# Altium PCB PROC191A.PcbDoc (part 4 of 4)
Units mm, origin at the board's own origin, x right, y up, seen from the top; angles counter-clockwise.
Board outline 150 x 100 mm, 6 copper layers (L1, L2, L3, L4, L5, L6), stack 1.608 mm thick; 309 components, 191 nets, 851 pads, 778 vias.
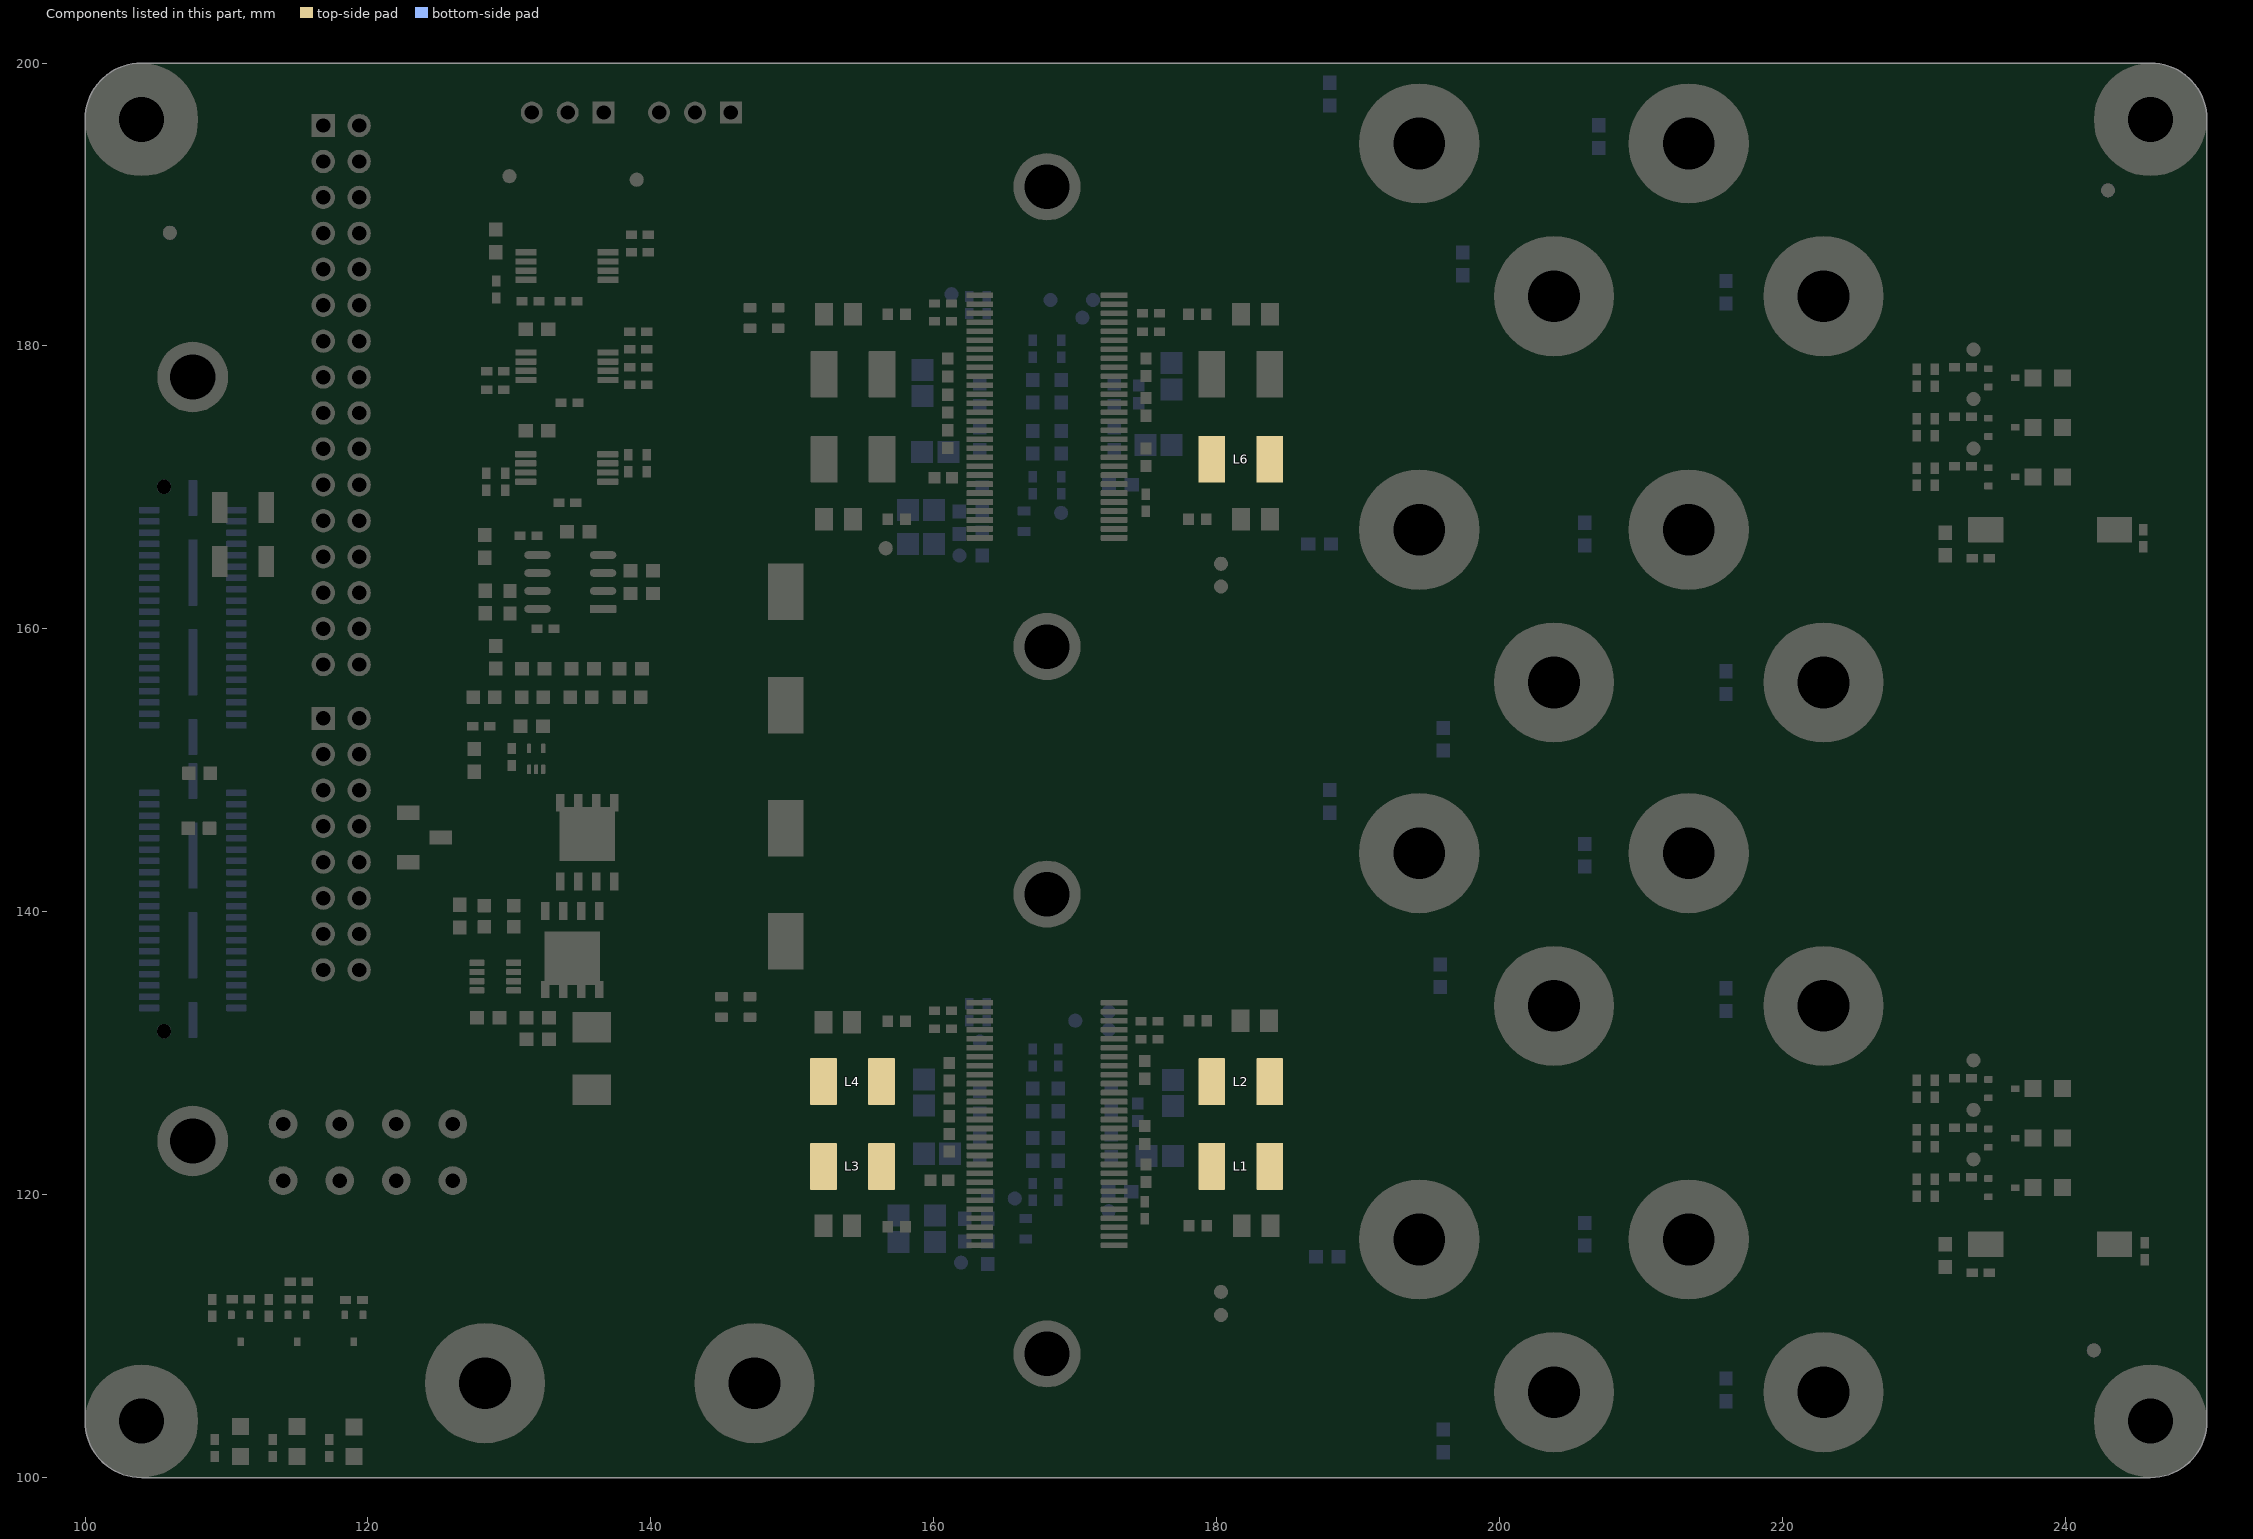
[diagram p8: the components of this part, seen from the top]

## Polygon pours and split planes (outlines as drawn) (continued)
PVDD on L3 "L3_PVDD_P025" (solid, remove dead copper, pour order 25): 131.911,150 131.911,142 158.5,142 160.5,144 160.5,156.5 158.5,158.5 142,158.5 140,156.5 140,150
OUT_1P_J1 on L3 "L3_OUT_1P_J1_P032" (solid, remove dead copper, pour order 32): 150.75,130.5 154.5,130.5 154.5,134.5 156,136 170.5,136 170.5,138.25 153.26,138.25 150.75,135.74
OUT_2P_J1 on L3 "L3_OUT_2P_J1_P033" (solid, remove dead copper, pour order 33): 150.546,119.494 154.296,119.494 154.296,115.744 156.04,114 170.296,114 170.296,111.5 153.299,111.5 150.546,114.253
PVDD_CONN on L3 "L3_PVDD_CONN_P040" (solid, remove dead copper, pour order 40): 137.449,139 131.911,139 131.911,100 153.015,100 153.015,111.21 150.225,114 150.225,125.829 140,135.604 140,139
VDDIO on L3 "L3_VDDIO_P050" (solid, remove dead copper, pour order 50): 114,128 151,128 153.31,130.31 153.31,190.5 118,190.5 110.49,182.99 110.49,154 113,154 113,129
OUT_1M_J1 on L3 "L3_OUT_1M_J1_P065" (solid, remove dead copper, pour order 65): 166,128 166,129.75 164,131.75 156.75,131.75 156.75,133.5 170.5,133.5 170.5,135.75 156,135.75 154.5,134.25 154.5,130.5 155.5,129.5 162,129.5 163.5,128
OUT_2M_J1 on L3 "L3_OUT_2M_J1_P066" (solid, remove dead copper, pour order 66): 166,121.976 166,120.254 163.746,118 156.75,118 156.75,116.463 170.5,116.463 170.5,114.226 156,114.226 154.5,115.726 154.5,118.726 156.024,120.25 162.024,120.25 163.75,121.976
OUT_4P_J1 on L3 "L3_OUT_4P_J1_P067" (solid, remove dead copper, pour order 67): 194.5,114.5 194.5,119.75 185.75,119.75 185.75,117 188.25,114.5
OUT_4M_J1 on L3 "L3_OUT_4M_J1_P069" (solid, remove dead copper, pour order 69): 185.5,124.5 211.5,124.5 216.5,119.5 210.75,113.75 207.533,117 196.75,117 193.75,120 185.5,120
OUT_3P0 on L3 "L3_OUT_3P0_P075" (solid, remove dead copper, pour order 75): 169.75,175 174.547,175 176.047,176.5 178.692,176.5 178.692,179.5 175.75,179.5 173,176.75 169.75,176.75
OUT_1P0 on L3 "L3_OUT_1P0_P078" (solid, remove dead copper, pour order 78): 166.102,176.75 166.102,175 160.809,175 159.691,176.5 157,176.5 157,179.5 159.75,179.5 162.042,176.75
OUT_2P0 on L3 "L3_OUT_2P0_P080" (solid, remove dead copper, pour order 80): 166.102,175 160.75,175 159.25,173.5 157,173.5 157,170.551 159.949,170.551 162.5,173.25 166.102,173.25
OUT_4P0 on L3 "L3_OUT_4P0_P085" (solid, remove dead copper, pour order 85): 169.75,173.25 169.75,175 174.562,175 175.812,173.75 178.692,173.75 178.692,170.75 175.75,170.75 173.25,173.25
OUT_3P_J1 on L3 "L3_OUT_3P_J1_P118" (solid, remove dead copper, pour order 118): 206,135.5 206,130.5 185.5,130.5 185.5,133 188,135.5
OUT_4M_J1 on L3 "L3_OUT_4M_J1_P119" (solid, remove dead copper, pour order 119): 170,122.75 173,122.75 175.25,120.5 178,120.5 182,124.5 186.25,124.5 186.25,120 183.75,120 180.75,117 175.25,117 171.5,120.75 170,120.75
OUT_3M_J1 on L3 "L3_OUT_3M_J1_P121" (solid, remove dead copper, pour order 121): 170,127.75 173,127.75 175,129.75 178.5,129.75 182.25,126 186.25,126 186.25,130.25 183.75,130.25 180.75,133.25 175,133.25 171.5,129.75 170,129.75
OUT_3P1 on L3 "L3_OUT_3P1_P122" (solid, remove dead copper, pour order 122): 169.75,125 174.547,125 176.047,126.5 178.692,126.5 178.692,129.5 175.75,129.5 173,126.75 169.75,126.75
OUT_1P1 on L3 "L3_OUT_1P1_P123" (solid, remove dead copper, pour order 123): 166.102,126.75 166.102,125 160.809,125 159.691,126.5 157,126.5 157,129.5 159.75,129.5 162.042,126.75
OUT_2P1 on L3 "L3_OUT_2P1_P124" (solid, remove dead copper, pour order 124): 166.102,125 160.75,125 159.25,123.5 157,123.5 157,120.551 159.949,120.551 162.5,123.25 166.102,123.25
OUT_3P_J1 on L3 "L3_OUT_3P_J1_P125" (solid, remove dead copper, pour order 125): 182.75,130.5 182.75,133.125 187,133.125 187,130.5
OUT_4P_J1 on L3 "L3_OUT_4P_J1_P126" (solid, remove dead copper, pour order 126): 182.75,117 182.75,119.75 187,119.75 187,117
OUT_4P1 on L3 "L3_OUT_4P1_P127" (solid, remove dead copper, pour order 127): 169.75,123.25 169.75,125 174.562,125 175.812,123.75 178.692,123.75 178.692,120.75 175.75,120.75 173.25,123.25
OUT_2P_J1 on L3 "L3_OUT_2P_J1_P128" (solid, remove dead copper, pour order 128): 170,111.5 179.29,102.21 203.835,102.21 203.835,110.21 182.79,110.21 179,114 170,114
OUT_1M_J1 on L3 "L3_OUT_1M_J1_P129" (solid, remove dead copper, pour order 129): 170,135.75 180,135.75 184.5,140.25 194,140.25 198,144.25 207.75,144.25 210.75,147.25 216.375,141.625 211.75,137 187.25,137 183.75,133.5 170,133.5
OUT_3M_J1 on L3 "L3_OUT_3M_J1_P130" (solid, remove dead copper, pour order 130): 185.5,126 221,126 226,131 220.25,136.75 217,133.5 207.405,133.5 204.155,130.25 185.5,130.25
OUT_2M_J1 on L3 "L3_OUT_2M_J1_P139" (solid, remove dead copper, pour order 139): 170,116.447 170,114.226 178.774,114.226 182.75,110.25 202.5,110.25 206.5,106.25 217.5,106.25 220.25,103.25 225.875,108.875 221,113.75 185.5,113.75 182.803,116.447 179.5,116.447
OUT_1P_J1 on L3 "L3_OUT_1P_J1_P141" (solid, remove dead copper, pour order 141): 170,138.25 180,148.25 194.31,148.25 194.31,140.25 184.5,140.25 180.25,136 170,136
GND on L3 "L3_GND_P145" (solid, remove dead copper, pour order 145): 104,200 246,200 cw(c246,196) 250,196 250,104 cw(c246,104) 246,100 104,100 cw(c104,104) 100,104 100,196 cw(c104,196)
GND on L4 "L4_GND_P185" (solid, remove dead copper, pour order 185): 104,200 246,200 cw(c246,196) 250,196 250,104 cw(c246,104) 246,100 104,100 cw(c104,104) 100,104 100,196 cw(c104,196)
VSYS5V0 on L4 "L4_VSYS5V0_P143" (solid, remove dead copper, pour order 143): 172,193 172,196 172.5,196.5 184.5,196.5 190.5,190.5 230,190.5 230.458,190.042 230.458,187.458 230,187 190,187 184.5,192.5 172.5,192.5
VDDIO on L4 "L4_VDDIO_P144" (solid, remove dead copper, pour order 144): 161,183.5 161.5,183 180,183 185,178 218.25,178 218.75,177.5 218.75,175.5 218.25,175 184,175 179,180 161,180
PVDD on L4 "L4_PVDD_P184" (solid, remove dead copper, pour order 184): 148.47,146.47 163.53,146.47 176.5,133.5 176.5,117 174.5,115 148.5,115 147.25,116.25 147.25,145.25
VDDIO on L4 "L4_VDDIO_P150" (solid, remove dead copper, pour order 150): 162,131 162,133.5 161,134.5 146.5,134.5 145.5,133.5 145.5,131 146.5,130 161,130
VDDIO on L4 "L4_VDDIO_P154" (solid, remove dead copper, pour order 154): 162,180 162,182.5 161,183.5 148.5,183.5 147.5,182.5 147.5,180 148.5,179 161,179
PVDD on L4 "L4_PVDD_P169" (solid, remove dead copper, pour order 169): 149,180 175,180 176.75,178.25 176.75,153.75 174.5,151.5 148.5,151.5 147.5,152.5 147.5,178.5
PVDD_CONN on L2 "L2_PVDD_CONN_P022" (solid, remove dead copper, pour order 22): 132.444,138.342 136.444,138.342 136.444,135.342 132.444,135.342
PVDD on L2 "L2_PVDD_P146" (solid, remove dead copper, pour order 146): 156.351,157.414 159.541,157.414 159.541,154.269 156.351,154.269
GND on L2 "L2_GND_P172" (solid, remove dead copper, pour order 172): 104,200 246,200 cw(c246,196) 250,196 250,104 cw(c246,104) 246,100 104,100 cw(c104,104) 100,104 100,196 cw(c104,196)
PVDD on L2 "L2_PVDD_P171" (solid, remove dead copper, pour order 171): 133.5,147 137.5,147 137.5,144 133.5,144
PVDD on L2 "L2_PVDD_P024" (solid, remove dead copper, pour order 24): 156.351,146.264 159.541,146.264 159.541,143.119 156.351,143.119
GND on L6 "L6_GND_P175" (solid, remove dead copper, pour order 175): 104,200 246,200 cw(c246,196) 250,196 250,104 cw(c246,104) 246,100 104,100 cw(c104,104) 100,104 100,196 cw(c104,196)
VDDIO on L6 "L6_VDDIO_P152" (solid, remove dead copper, pour order 152): 110,166.5 113,166.5 113,162.8 110,162.8
VSYS5V0 on L6 "L6_VSYS5V0_P148" (solid, remove dead copper, pour order 148): 110,170.5 113,170.5 113,166.5 110,166.5
PVDD on L6 "L6_PVDD_P035" (solid, remove dead copper, pour order 35): 175.6,177.3 177.8,177.3 177.8,173.5 175.6,173.5
PVDD on L6 "L6_PVDD_P034" (solid, remove dead copper, pour order 34): 158.3,176.9 160.5,176.9 160.5,173.1 158.3,173.1
PVDD on L6 "L6_PVDD_P138" (solid, remove dead copper, pour order 138): 175.517,126.8 177.7,126.8 177.7,123 175.517,123
PVDD on L6 "L6_PVDD_P137" (solid, remove dead copper, pour order 137): 160.483,122.65 158.3,122.65 158.3,126.8 160.483,126.8
OUT_2P1 on L6 "L6_OUT_2P1_P136" (solid, remove dead copper, pour order 136): 168,123.5 162.75,123.5 162.75,125 168,125
OUT_4P1 on L6 "L6_OUT_4P1_P135" (solid, remove dead copper, pour order 135): 168,125 173.25,125 173.25,123.5 168,123.5
OUT_1P1 on L6 "L6_OUT_1P1_P110" (solid, remove dead copper, pour order 110): 168,125 162.75,125 162.75,126.5 168,126.5
OUT_3P1 on L6 "L6_OUT_3P1_P109" (solid, remove dead copper, pour order 109): 168,126.5 173.25,126.5 173.25,125 168,125
OUT_2P0 on L6 "L6_OUT_2P0_P108" (solid, remove dead copper, pour order 108): 167.796,173.5 162.75,173.5 162.75,175 167.796,175
OUT_3P0 on L6 "L6_OUT_3P0_P036" (solid, remove dead copper, pour order 36): 168,176.5 173.25,176.5 173.25,175 168,175
OUT_4P0 on L6 "L6_OUT_4P0_P107" (solid, remove dead copper, pour order 107): 168,175 173.25,175 173.25,173.5 168,173.5
OUT_1P0 on L6 "L6_OUT_1P0_P037" (solid, remove dead copper, pour order 37): 168,175 162.75,175 162.75,176.5 168,176.5
GND on L5 "L5_GND_P174" (solid, remove dead copper, pour order 174): 104,200 246,200 cw(c246,196) 250,196 250,104 cw(c246,104) 246,100 104,100 cw(c104,104) 100,104 100,196 cw(c104,196)

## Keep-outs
Keep-Out Layer:
  text ".Layer_Name" at 14.656,-21.806 h1.52

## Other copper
L1:
  text ".Layer_Name" at 14.656,-21.806 h1.52
L6:
  text ".Layer_Name" at 14.656,-21.806 h1.52

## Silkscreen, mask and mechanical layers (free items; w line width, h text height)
Top Overlay:
  rectangle: 236,161 238,162.5
  rectangle: 240,163 242,164.5
  rectangle: 240,112.5 242,114
  rectangle: 236,110.5 238,112
  lines w0.2: 201.5,113.34 cw(c201.5,114.84) 201.5,116.34 cw(c201.5,114.84) 201.5,113.34 ; 201.5,140.645 cw(c201.5,142.145) 201.5,143.645 cw(c201.5,142.145) 201.5,140.645 ; 201.5,163.5 cw(c201.5,165) 201.5,166.5 cw(c201.5,165) 201.5,163.5 ; 201.5,190.81 ccw(c201.5,192.31) 201.5,193.81 ccw(c201.5,192.31) 201.5,190.81 ; 206.17,113.34 cw(c206.17,114.84) 206.17,116.34 cw(c206.17,114.84) 206.17,113.34 ; 206.17,140.645 cw(c206.17,142.145) 206.17,143.645 cw(c206.17,142.145) 206.17,140.645 ; 206.17,190.81 ccw(c206.17,192.31) 206.17,193.81 ccw(c206.17,192.31) 206.17,190.81 ; 206.34,163.51 cw(c206.34,165.01) 206.34,166.51 cw(c206.34,165.01) 206.34,163.51 ; 211,180.015 cw(c211,181.515) 211,183.015 cw(c211,181.515) 211,180.015 ; 211.025,102.545 cw(c211.025,104.045) 211.025,105.545 cw(c211.025,104.045) 211.025,102.545 ; 211.025,129.85 cw(c211.025,131.35) 211.025,132.85 cw(c211.025,131.35) 211.025,129.85 ; 211.025,152.71 cw(c211.025,154.21) 211.025,155.71 cw(c211.025,154.21) 211.025,152.71 ; 215.5,180.015 cw(c215.5,181.515) 215.5,183.015 cw(c215.5,181.515) 215.5,180.015 ; 215.695,102.545 cw(c215.695,104.045) 215.695,105.545 cw(c215.695,104.045) 215.695,102.545 ; 215.695,129.85 cw(c215.695,131.35) 215.695,132.85 cw(c215.695,131.35) 215.695,129.85 ; 215.695,152.71 cw(c215.695,154.21) 215.695,155.71 cw(c215.695,154.21) 215.695,152.71 ; 222,113.84 cw(c222,116.84) 222,119.84 227,119.84 cw(c227,116.84) 227,113.84 222,113.84 ; 222,164.005 cw(c222,167.005) 222,170.005 227,170.005 cw(c227,167.005) 227,164.005 222,164.005 ; 223,141.145 cw(c223,144.145) 223,147.145 228,147.145 cw(c228,144.145) 228,141.145 223,141.145 ; 223,190.31 cw(c223,193.31) 223,196.31 228,196.31 cw(c228,193.31) 228,190.31 223,190.31 ; 232.525,130.35 cw(c232.525,133.35) 232.525,136.35 237.525,136.35 cw(c237.525,133.35) 237.525,130.35 232.525,130.35 ; 232.525,153.21 cw(c232.525,156.21) 232.525,159.21 237.525,159.21 cw(c237.525,156.21) 237.525,153.21 232.525,153.21 ; 232.525,180.515 cw(c232.525,183.515) 232.525,186.515 237.525,186.515 cw(c237.525,183.515) 237.525,180.515 232.525,180.515 ; 232.716,103.045 cw(c232.716,106.045) 232.716,109.045 237.716,109.045 cw(c237.716,106.045) 237.716,103.045 232.716,103.045
  lines w0.254: 125.5,143.5 126.5,143.5 ; 125.5,147 126.5,147 ; 140.5,150 158,150 244.5,150 ; 235.5,110.5 242.5,110.5 242.5,112 235.5,112 235.5,110.5 ; 235.5,112.5 242.5,112.5 242.5,114 235.5,114 235.5,112.5 ; 235.5,161 242.5,161 242.5,162.5 235.5,162.5 235.5,161 ; 235.5,163 242.5,163 242.5,164.5 235.5,164.5 235.5,163
  text "GND 1" at 111.863,195.199 h0.76
  text "2 GND" at 121.056,195.199 h0.76
  text "UART_TX 3" at 108.562,192.723 h0.76
  text "4 AECCLKOUT" at 121.056,192.659 h0.76
  text "T0-CH1" at 221.25,192.56 h1.5
  text "FAN0" at 130.96,191.92 h1
  text "FAN1" at 139.85,191.92 h1
  text "M" at 205.67,191.56 h1.5
  text "P" at 200.75,191.31 h1.5
  text "TAS0" at 180.25,190.75 h1.5
  text "MCASPX_ACLKR 5" at 104.753,190.183 h0.76
  text "6 AECCLKIN" at 121.056,190.119 h0.76
  text "GND 7" at 111.609,187.579 h0.76
  text "8 GND" at 121.056,187.579 h0.76
  text "MCASPX_FSX 9" at 106.276,185.103 h0.76
  text "10 FSYNC1" at 121.056,185.039 h0.76
  text "T0-CH3" at 230.775,182.765 h1.5
  text "MCASPX_FSR 11" at 105.896,182.563 h0.76
  text "12 FSYNC2" at 121.056,182.499 h0.76
  text "M" at 215,180.765 h1.5
  text "P" at 210.25,180.515 h1.5
  text "GND 13" at 110.974,179.959 h0.76
  text "14 GND" at 121.056,179.959 h0.76
  text "TAS0" at 142.65,179.15 h1
  text "I2C ADDR" at 142.65,177.65 h1
  text "15" at 114.021,177.419 h0.76
  text "16 I2CSCL" at 121.056,177.419 h0.76
  text "FLT" at 241.4,177.4 h1
  text "17" at 114.021,174.879 h0.76
  text "18 I2CSDA" at 121.056,174.879 h0.76
  text "SBY" at 241.25,173.5 h1
  text "TAS0 / STATUS" at 222.5,173 h1
  text "MCASPX_AR2 19" at 105.642,172.403 h0.76
  text "20 SPICLK" at 121.056,172.339 h0.76
  text "PWD" at 241.4,170.4 h1
  text "21" at 114.148,169.799 h0.76
  text "22 SPICS0" at 121.056,169.799 h0.76
  text "23" at 113.894,167.259 h0.76
  text "24 SPICS1" at 121.056,167.259 h0.76
  text "T0-CH4" at 220.25,166.255 h1.5
  text "25" at 113.894,164.719 h0.76
  text "26 SPID0" at 121.056,164.719 h0.76
  text "M" at 205.84,164.26 h1.5
  text "P" at 200.75,164 h1.5
  text "HIGH" at 243.15,163 h1
  text "28 SPID1" at 121.056,162.179 h0.76
  text "TAS0 GPIO1" at 225.418,161.65 h1
  text "MCASPX_S6 27" at 106.124,161.2 h0.76
  text "LOW" at 243.15,161 h1
  text "MCASPX_S7 29" at 106.276,159.703 h0.76
  text "30 UARTTX" at 120.904,158.75 h0.76
  text "GND 31" at 111.101,157.099 h0.76
  text "32 UARTRX" at 120.904,156.947 h0.76
  text "T0-CH2" at 230.775,155.46 h1.5
  text "M" at 215.195,153.46 h1.5
  text "MCASPY_ACLKX 1" at 105.007,153.337 h0.76
  text "2" at 121.056,153.289 h0.76
  text "P" at 210.275,153.21 h1.5
  text "PORZ" at 135.975,152.587 h1
  text "FANOUT" at 135.975,151.229 h1
  text "GND 3" at 111.609,150.749 h0.76
  text "4" at 121.057,150.749 h0.76
  text "5" at 114.656,148.209 h0.76
  text "6" at 121.057,148.209 h0.76
  text "RESET / STATZ" at 127,146.05 h1
  text "8" at 121.057,145.669 h0.76
  text "GND 7" at 111.456,144.1 h0.76
  text "T1-CH1" at 221.25,143.395 h1.5
  text "MCASPY_AFSX 9" at 105.515,143.193 h0.76
  text "PORZ" at 127.15,143.152 h1
  text ".PRJ_Title" at 233.15,142.15 h1
  text "M" at 205.67,141.395 h1.5
  text "P" at 200.75,141.145 h1.5
  text "TAS1" at 180.75,140.75 h1.5
  text "GND 11" at 111.228,140.589 h0.76
  text "12" at 121.056,140.589 h0.76
  text ".PRJ_Number" at 233.15,140.15 h1
  text ".PCB_Rev" at 240.15,140.15 h1
  text "MCASPY_AFSR 13" at 104.88,138.113 h0.76
  text "14" at 121.056,138.049 h0.76
  text "GND 15" at 110.974,135.509 h0.76
  text "16" at 121.133,135.509 h0.76
  text "T1-CH3" at 230.775,132.6 h1.5
  text "M" at 215.195,130.6 h1.5
  text "P" at 210.275,130.35 h1.5
  text "TAS1" at 142.15,129.65 h1
  text "I2C ADDR" at 142.15,128.15 h1
  text "FLT" at 241.4,127.15 h1
  text "PORZ" at 125.92,126.746 h1.52 r45
  text "GND" at 113.982,126.492 h1.52 r45
  text "GPIO1" at 118.046,126.492 h1.52 r45
  text "GPIO0" at 121.856,126.492 h1.52 r45
  text "SBY" at 241.4,123.65 h1
  text "TAS1 / STATUS" at 222.5,122.75 h1
  text "PWD" at 241.4,120.15 h1
  text "GND" at 112.712,116.84 h1.52 r45
  text "PVDD" at 124.142,116.332 h1.52 r45
  text "T1-CH4" at 220.25,116.09 h1.5
  text "VDDIO" at 119.824,115.824 h1.52 r45
  text "VSYS5V0" at 114.49,114.554 h1.52 r45
  text "M" at 205.67,114.09 h1.5
  text "P" at 200.75,113.84 h1.5
  text "HIGH" at 243.15,112.5 h1
  text "TAS1 GPIO1" at 226.001,112 h1
  text "GND" at 133.778,111.25 h1.5
  text "PVDD" at 151.7,111.25 h1.5
  text "LOW" at 243.15,110.5 h1
  text "PORZ" at 118.369,105.556 h1 r45
  text "IOVDD" at 109.635,105.512 h1 r45
  text "PVDD" at 114.35,105.512 h1 r45
  text "T1-CH2" at 230.966,105.295 h1.5
  text "M" at 215.195,103.295 h1.5
  text "P" at 210.275,103.045 h1.5
  text ".Layer_Name" at 14.656,-22.695 h1.52
Bottom Overlay:
  text ".Layer_Name" at 14.656,-21.806 h1.52
Top Paste:
  text ".Layer_Name" at 14.656,-21.806 h1.52
Bottom Paste:
  text ".Layer_Name" at 14.656,-21.806 h1.52
Top Solder:
  region: 240,100 240,101.5 241.5,103 250,103 250,100
  region: 156,100 156,101.5 157.5,103 193,103 194.5,101.5 194.5,100
  region: 103,100 100,100 100,128.5 101.5,128.5 103,127
  region: 100,197 100,200 113.5,200 113.5,198.5 112,197
  region: 149.5,198.5 149.5,200 185.5,200 185.5,198.5 184,197 151,197
  region: 219.5,198.5 219.5,200 250,200 250,197 221,197
  region: 101.5,137.5 100,137.5 100,200 103,200 103,139
  region: 250,100 247,100 247,200 250,200
  text ".Layer_Name" at 14.656,-21.806 h1.52
  text ".Layer_Name" at 14.656,-21.806 h1.52
Bottom Solder:
  region: 103,103 100,103 100,128.5 101.5,128.5 103,127
  region: 231,100 231,101.5 232.5,103 250,103 250,100
  region: 100,197 100,200 113.5,200 113.5,198.5 112,197
  region: 149.5,198.5 149.5,200 185.5,200 185.5,198.467 184.032,197 151,197
  region: 219.5,198.5 219.5,200 250,200 250,197 221,197
  region: 100,100 100,103 119,103 120.32,101.68 120.32,100
  region: 101.5,173.5 100,173.5 100,200 103,200 103,175
  region: 250,100 247,100 247,200 250,200
  region: 156,100 156,101.46 157.54,103 190.5,103 192,101.5 192,100
  text ".Layer_Name" at 14.656,-21.806 h1.52
Drill Guide:
  text ".Layer_Name" at 14.656,-21.806 h1.52
M1 Board Outline:
  the board outline again, w0.254
  text ".Layer_Name" at 14.656,-21.806 h1.52
M2 Board Dimensions:
  circle w0.254: c246,104 r1.6
  circle w0.254: c107.62,177.8 r1.6
  circle w0.254: c107.62,123.8 r1.6
  circle w0.254: c104,104 r1.6
  circle w0.254: c104,196 r1.6
  circle w0.254: c246,196 r1.6
  rectangle: 3.175,-10.16 12.7,-6.985
  rectangle: 0,-6.985 3.175,-3.81
  lines w0.178: 0,-6.985 25.4,-6.985 ; 3.175,-10.16 3.175,-3.81 ; 6.35,-10.16 6.35,-3.81 ; 12.7,-10.16 12.7,-3.81 ; 19.05,-10.16 19.05,-3.81 ; 0,-10.16 0,-3.81 25.4,-3.81 25.4,-10.16 0,-10.16
  lines w0.2: 89,152 90,151 ; 106.62,209 107.62,210 ; 119,218 120,219
  lines w0.254: 77,150.8 107.62,150.8 ; 86,154 90,154 90,151 91,152 ; 98.62,210 107.62,210 106.62,211 ; 99,123.8 107.62,123.8 ; 99,177.8 107.62,177.8 ; 99,219 120,219 119,220 ; 107.62,95 107.62,215 ; 107.62,170.9 107.62,205 ; 120,85 120.32,235
  text "BASEBOARD EDGE" at 77.152,218.152 h1.52
  text "VERT CENTERLINE  / AEC CONNECTOR" at 74,208.924 h1.52
  text "HORZ CENTERLINE  / AEC CONNECTOR" at 61.588,152 h1.52
  text ".Layer_Name" at 14.656,-21.806 h1.52
M3 3D STEP Top:
  text ".Layer_Name" at 14.656,-21.806 h1.52
M4 3D STEP Bottom:
  text ".Layer_Name" at 14.656,-21.806 h1.52
M5 Assembly Top:
  lines w0.254: -7.417,-23.626 160.223,-23.626 ; -7.417,-18.462 160.274,-18.462 ; -7.417,-13.297 -7.417,-28.791 94.31,-28.791 160.274,-28.791 160.274,-13.297 -7.404,-13.297 -7.404,-28.791 32.614,-28.791 ; 55.194,-28.791 55.194,-13.297 ; 87.376,-18.462 87.376,-13.297 ; 108.712,-18.462 108.712,-13.297 ; 124.511,-28.956 124.511,-23.804
  text "COMPONENTS MARKED 'DNP' SHOULD NOT BE POPULATED." at 29.299,-8.09 h1.52
  text "ASSEMBLY VARIANT:" at 29.286,-11.024 h1.52
  text ".VariantName" at 55.601,-11.024 h1.52
  text "PCB VIEWED FROM TOP SIDE" at -5.804,-16.654 h1.52
  text "BOARD #:" at 57.099,-16.654 h1.52
  text ".PRJ_Number" at 70.955,-16.654 h1.52
  text "REV:" at 92.405,-16.654 h1.52
  text ".PCB_Rev" at 99.809,-16.654 h1.52
  text "SVN REV:" at 113.69,-16.654 h1.52
  text ".VersionControl_RevNumber" at 126.543,-16.654 h1.52
  text "PLOT NAME =" at -5.804,-27.034 h1.52
  text ".plot_File_Name" at 14.656,-27.034 h1.52
  text "GENERATED    :" at 57.15,-27.034 h1.52
  text ".Print_Date" at 79.235,-27.034 h1.52
  text ".Print_Time" at 97.752,-27.034 h1.52
  text "TEXAS INSTRUMENTS" at 129.87,-27.034 h1.52
M6 Assembly Bottom:
  lines w0.254: -7.429,-18.474 160.261,-18.474 ; -7.379,-23.639 160.261,-23.639 ; 28.334,-28.969 28.334,-23.817 ; 44.133,-18.474 44.133,-13.31 ; 65.468,-18.474 65.468,-13.31 ; 97.65,-28.804 97.65,-13.31 ; 120.231,-28.804 160.249,-28.804 160.249,-13.31 -7.429,-13.31 -7.429,-28.804 58.534,-28.804 160.261,-28.804 160.261,-13.31
  text "COMPONENTS MARKED 'DNP' SHOULD NOT BE POPULATED." at 154.991,-8.077 h1.52
  text ".VariantName" at 128.473,-11.024 h1.52
  text "ASSEMBLY VARIANT:" at 154.864,-11.024 h1.52
  text ".VersionControl_RevNumber" at 26.302,-16.667 h1.52
  text "SVN REV:" at 39.154,-16.667 h1.52
  text ".PCB_Rev" at 53.035,-16.667 h1.52
  text "REV:" at 60.439,-16.667 h1.52
  text ".PRJ_Number" at 81.89,-16.667 h1.52
  text "BOARD #:" at 95.745,-16.667 h1.52
  text "PCB VIEWED FROM BOTTOM SIDE" at 158.648,-16.667 h1.52
  text "TEXAS INSTRUMENTS" at 22.974,-27.047 h1.52
  text ".Print_Time" at 55.093,-27.047 h1.52
  text ".Print_Date" at 73.609,-27.047 h1.52
  text "GENERATED    :" at 95.694,-27.047 h1.52
  text ".plot_File_Name" at 138.189,-27.047 h1.52
  text "PLOT NAME =" at 158.648,-27.047 h1.52
M9 Title Sheet:
  drawing of 63 lines, arcs and shapes, not listed
  text "1" at 35.293,466.75 h1.78
  text "2" at 136.766,466.75 h1.78
  text "3" at 238.239,466.75 h1.78
  text "4" at 339.865,466.75 h1.78
  text "5" at 441.423,466.75 h1.78
  text "6" at 542.98,466.75 h1.78
  text "7" at 644.623,466.75 h1.78
  text "8" at 746.096,466.75 h1.78
  text "A" at -11.874,405.841 h1.78
  text "A" at 793.305,405.841 h1.78
  text "B" at -11.874,278.841 h1.78
  text "B" at 793.305,278.841 h1.78
  text "C" at -11.874,151.841 h1.78
  text "C" at 793.305,151.841 h1.78
  text "D" at -11.874,24.841 h1.78
  text "D" at 793.305,24.841 h1.78
  text "PROJECT TITLE:" at 714.947,6.823 h1.14
  text ".PRJ_Title" at 716.216,3.436 h1.78
  text "DESIGNED FOR:" at 714.947,-0.823 h1.14
  text ".PRJ_Customer" at 716.216,-4.379 h1.78
  text "FILE NAME:" at 714.947,-8.443 h1.14
  text ".PCB_File_Name_No_Path" at 716.216,-11.491 h1.78
  text "Texas Instruments (TI) and/or its licensors do not warrant the accuracy or completeness of this specification" at 588.721,-15.601 h1.14
  text "ENGINEER:" at 714.947,-15.809 h1.14
  text "LAYOUT BY:" at 753.173,-15.809 h1.14
  text "or any information contained therein. TI and/or its licensors do not warrant that this design will meet" at 587.579,-18.463 h1.14
  text ".PRJ_Engineer" at 716.216,-19.746 h1.78
  text ".PCB_Layout" at 754.456,-19.746 h1.78
  text "the specifications, will be suitable for your application or fit for any particular purpose, or will operate in" at 587.579,-21.325 h1.14
  text ".Layer_Name" at 14.656,-21.806 h1.52
  text "ALTIUM DESIGNER VERSION:" at 753.173,-23.683 h1.14
  text "an implementation. TI and/or its licensors do not warrant that the design is production worthy. You should" at 587.579,-24.187 h1.14
  text "completely validate and test your design implementation to confirm the system functionality for your application." at 588.721,-27.048 h1.14
  text ".print_Scale" at 716.216,-27.069 h1.78
  text ".Application_BuildNumber" at 754.456,-27.069 h1.78
  text "1" at 35.293,-33.503 h1.78
  text "2" at 136.766,-33.503 h1.78
  text "3" at 238.239,-33.503 h1.78
  text "4" at 339.865,-33.503 h1.78
  text "5" at 441.423,-33.503 h1.78
  text "6" at 542.98,-33.503 h1.78
  text "7" at 644.623,-33.503 h1.78
  text "8" at 746.096,-33.503 h1.78
M10 Fab Notes:
  drawing of 189 lines, arcs and shapes, not listed
  text "DESIGN INFORMATION" at 741.376,161.675 h1.52
  text "MIN. TRACK WIDTH:" at 725.004,158.319 h1.52
  text "7" at 752.848,158.32 h1.52
  text "MM" at 756.779,158.319 h1.52
  text "MIN. CLEARANCE:" at 725.004,155.167 h1.52
  text "5" at 752.881,155.169 h1.52
  text "MIL" at 756.779,155.167 h1.52
  text "19" at 752.231,152.052 h1.52
  text "MIN. VIA PAD SIZE:" at 725.004,152.014 h1.52
  text "MIL" at 756.779,152.014 h1.52
  text "0.05mm (2MIL)" at 742.657,148.714 h1.52
  text "MINIMUM ANNULAR RING" at 716.641,148.506 h1.52
  text "EXTERNAL" at 760.64,148.506 h1.52
  text "PER" at 721.721,145.708 h1.52
  text "IPC-D-275 CLASS 2 LEVEL C" at 727.309,145.708 h1.52
  text "MIL, HOLES" at 765.11,143.156 h1.52
  text "+/-" at 755.142,142.938 h1.52
  text "+/-" at 776.834,142.938 h1.52
  text "REGISTRATION TOLERANCES:" at 716.641,142.911 h1.52
  text "METAL" at 747.116,142.911 h1.52
  text "5" at 761.751,142.911 h1.52
  text "3" at 782.909,142.911 h1.52
  text "MIL" at 785.862,142.911 h1.52
  text "HOLE SIZE TOLERANCE (UNLESS OTHERWISE SPECIFIED):" at 716.641,140.414 h1.52
  text "+/-" at 776.834,140.341 h1.52
  text "3" at 782.909,140.314 h1.52
  text "MIL" at 785.862,140.314 h1.52
  text "MATERIAL:" at 714.742,136.818 h1.52
  text "FR-4 High Tg" at 739.798,133.553 h1.52
  text "X" at 736.129,133.35 h1.52
  text "FR-4" at 725.436,133.235 h1.52
  text "OTHER" at 763.231,133.235 h1.52
  text "62 MIL (1.6mm) +/-10%" at 733.566,129.602 h1.52
  text "X" at 730.516,129.54 h1.52
  text "THICKNESS:" at 716.641,129.394 h1.52
  text "OTHER" at 766.203,129.394 h1.52
  text "TOLERANCE:" at 716.641,125.88 h1.52
  text "X" at 738.187,125.88 h1.52
  text "ANSI IPC-6012 TYPE 3 CLASS 2" at 742.708,125.88 h1.52
  text "OTHER +/-" at 742.708,122.218 h1.52
  text "BOW & TWIST:" at 716.641,118.53 h1.52
  text "X" at 738.187,118.53 h1.52
  text "ANSI IPC-6012 TYPE 3 CLASS 2" at 742.708,118.53 h1.52
  text "OTHER +/-" at 742.708,114.804 h1.52
  text "DRILLING:" at 714.742,111.486 h1.52
  text "NC_DRILL FILES" at 759.472,108.815 h1.52
  text "REFERENCE:" at 716.641,108.715 h1.52
  text "X" at 733.335,108.712 h1.52
  text "AS SHOWN" at 737.856,108.715 h1.52
  text "X" at 756.221,108.715 h1.52
  text "OTHER" at 767.041,105.101 h1.52
  text "PTH COPPER THICKNESS:" at 716.633,105.012 h1.52
  text "X" at 745.57,105.012 h1.52
  text "20-30 um" at 748.821,105.012 h1.52
  text "BOARD FINISH:" at 714.742,101.263 h1.52
  text "SILKSCREEN:" at 718.685,98.466 h1.52
  text "X" at 743.013,98.466 h1.52
  text "TOP" at 745.984,98.466 h1.52
  text "X" at 755.967,98.466 h1.52
  text "BOTTOM" at 758.964,98.466 h1.52
  text "SILKSCREEN COLOR:" at 718.685,94.524 h1.52
  text "WHITE" at 745.984,94.524 h1.52
  text "OTHER" at 758.964,94.524 h1.52
  text "X" at 743.136,94.482 h1.52
  text "X" at 762.416,92.464 h1.52 r180
  text "RED" at 773.615,90.905 h1.52
  text "GREEN" at 749.312,90.88 h1.52
  text "OTHER" at 765.009,90.88 h1.52
  text "SOLDER RESIST COLOR:" at 718.685,90.706 h1.52
  text "X" at 746.315,86.962 h1.52
  text "MATTE" at 749.312,86.962 h1.52
  text "SEMI-GLOSS" at 764.997,86.946 h1.52
  text "IMMERSION GOLD (ENIG)" at 741.692,82.574 h1.52
  text "ENEPIG" at 775.665,82.39 h1.52
  text "SURFACE FINISH:" at 714.742,82.365 h1.52
  text "X" at 737.171,82.365 h1.52
  text "IMM. TIN/SILVER OR EQUIV" at 723.113,78.877 h1.52
  text "OTHER" at 759.472,78.777 h1.52
  text "ARRAY/PANEL:" at 714.742,74.831 h1.52
  text "X" at 737.134,74.647 h1.52
  text "CUT AND TRIM PER M1 BOARD OUTLINE" at 741.692,74.622 h1.52
  text "N.C. ROUTE" at 741.692,71.168 h1.52
  text "V. SCORE" at 763.688,71.168 h1.52
  text "CERTIFICATION:" at 714.742,67.888 h1.52
  text "MATERIALS AND WORKMANSHIP FOR ALL PCBS" at 733.157,67.888 h1.52
  text "TO MEET OR EXCEED THE REQUIREMENTS OF:" at 733.157,65.499 h1.52
  text "X" at 723.95,62.232 h1.52
  text "ANSI IPC-A-600F CLASS ->" at 727.201,62.232 h1.52
  text "X" at 769.06,62.232 h1.52
  text "2" at 771.854,62.232 h1.52
  text "1" at 763.853,62.194 h1.52
  text "3" at 780.846,62.194 h1.52
  text "X" at 744.575,58.481 h1.52
  text "RoHS" at 747.826,58.481 h1.52
  text "OTHER" at 764.194,58.481 h1.52
  text "PER ORDER" at 774.279,58.481 h1.52
  text "ALL BOARDS MUST MEET OR EXCEED UL94-V0 REQUIREMENTS." at 715.442,54.574 h1.52
  text "PCB MUST BEAR THE UL94V-0 UL REGISTERED MATERIAL ID NUMBER" at 715.442,51.626 h1.52
  text "ADDITIONAL REQUIREMENTS:" at 714.742,47.322 h1.52
  text "MICROSECTION:" at 716.641,44.601 h1.52
  text "YES" at 739.647,44.601 h1.52
  text "REQUIRED" at 761.529,40.935 h1.52
  text "BARE BOARD ELEC. TEST:" at 716.641,40.863 h1.52
  text "NONE" at 749.807,40.863 h1.52
  text "X" at 758.532,40.863 h1.52
  text "PER ORDER" at 776.566,40.863 h1.52
  text "XX MIL VIAS REQUIRE NON-CONDUCTIVE FILL AND PLANARIZE" at 720.912,35.657 h1.5
  text "XX MIL VIAS REQUIRE CONDUCTIVE FILL AND PLANARIZE" at 721.116,33.016 h1.52
  text "OUTER XX MIL TRACES REQUIRE 50 OHM SINGLE-ENDED IMPEDANCE" at 721.091,28.866 h1.47
  text "LAYER 2 & 3 (INNER LAYERS) XX MIL WIDE, XX MIL SPACE / TRACES REQUIRE 100 OHM DIFFERENTIAL IMPEDANCE" at 720.887,22.879 h1.52
  text ".Layer_Name" at 14.656,-21.806 h1.52
M11 Gerber Information:
  lines w0.254: -7.417,-23.626 160.223,-23.626 ; -7.417,-18.462 160.274,-18.462 ; -7.417,-13.297 -7.417,-28.791 94.31,-28.791 160.274,-28.791 160.274,-13.297 -7.404,-13.297 -7.404,-28.791 32.614,-28.791 ; 55.194,-28.791 55.194,-13.297 ; 87.376,-18.462 87.376,-13.297 ; 108.712,-18.462 108.712,-13.297 ; 124.511,-28.956 124.511,-23.804
  text "ALL ARTWORK VIEWED FROM TOP SIDE" at -5.804,-16.654 h1.52
  text "BOARD #:" at 57.099,-16.654 h1.52
  text ".PRJ_Number" at 70.955,-16.654 h1.52
  text "REV:" at 92.405,-16.654 h1.52
  text ".PCB_Rev" at 99.809,-16.654 h1.52
  text "SVN REV:" at 113.69,-16.654 h1.52
  text ".VersionControl_RevNumber" at 126.543,-16.654 h1.52
  text "LAYER NAME =" at -5.804,-21.806 h1.52
  text "PLOT NAME =" at -5.804,-27.034 h1.52
  text ".plot_File_Name" at 14.656,-27.034 h1.52
  text "GENERATED    :" at 57.15,-27.034 h1.52
  text ".Print_Date" at 79.235,-27.034 h1.52
  text ".Print_Time" at 97.752,-27.034 h1.52
  text "TEXAS INSTRUMENTS" at 129.87,-27.034 h1.52
M12 Stackup:
  lines w0.381: 178.698,257.683 189.109,257.683 212.725,257.683 252.083,257.683 268.589,257.683 283.064,257.683 ; 178.698,260.731 189.109,260.731 212.725,260.731 252.083,260.731 268.589,260.731 283.064,260.731 ; 178.698,263.779 189.109,263.779 212.725,263.779 252.083,263.779 268.589,263.779 283.064,263.779 ; 178.698,266.827 189.109,266.827 212.725,266.827 252.083,266.827 268.589,266.827 283.064,266.827 ; 178.698,269.875 189.109,269.875 212.725,269.875 252.083,269.875 268.589,269.875 283.064,269.875 ; 178.698,272.923 189.109,272.923 212.725,272.923 252.083,272.923 268.589,272.923 283.064,272.923 ; 178.698,275.971 189.109,275.971 212.725,275.971 252.083,275.971 268.589,275.971 283.064,275.971 ; 178.698,279.019 189.109,279.019 212.725,279.019 252.083,279.019 268.589,279.019 283.064,279.019 ; 178.698,282.067 189.109,282.067 212.725,282.067 252.083,282.067 268.589,282.067 283.064,282.067 ; 178.698,285.115 189.109,285.115 212.725,285.115 252.083,285.115 268.589,285.115 283.064,285.115 ; 178.698,288.163 189.109,288.163 212.725,288.163 252.083,288.163 268.589,288.163 283.064,288.163 ; 178.698,291.211 189.109,291.211 212.725,291.211 252.083,291.211 268.589,291.211 283.064,291.211 ; 178.698,294.259 189.109,294.259 212.725,294.259 252.083,294.259 268.589,294.259 283.064,294.259 ; 178.698,297.307 189.109,297.307 212.725,297.307 252.083,297.307 268.589,297.307 283.064,297.307 ; 178.698,300.355 283.064,300.355 ; 189.109,303.403 189.109,254.635 ; 212.725,303.403 212.725,254.635 ; 252.083,303.403 252.083,254.635 ; 268.589,303.403 268.589,254.635 ; 189.109,254.635 178.698,254.635 178.698,303.403 283.064,303.403 283.064,254.635 268.589,254.635 ; 189.109,254.635 212.725,254.635 ; 212.725,254.635 252.083,254.635 ; 252.083,254.635 268.589,254.635
  text "Layer" at 180.476,301.117 h1.52
  text "Name" at 190.887,301.117 h1.52
  text "Material" at 214.503,301.117 h1.52
  text "Thickness" at 253.861,301.117 h1.52
  text "Constant" at 270.367,301.117 h1.52
  text "Top Overlay" at 190.887,298.069 h1.52
  text "Top Solder" at 190.887,295.021 h1.52
  text "Solder Resist" at 214.503,295.021 h1.52
  text "0.40mil" at 253.861,295.021 h1.52
  text "3.5" at 270.367,295.021 h1.52
  text "1" at 180.476,291.973 h1.52
  text "L1" at 190.887,291.973 h1.52
  text "Copper Foil, 1/2oz (17um)" at 214.503,291.973 h1.52
  text "0.71mil" at 253.861,291.973 h1.52
  text "Dielectric 1" at 190.887,288.925 h1.52
  text "Isola 370HR Core" at 214.503,288.925 h1.52
  text "3.94mil" at 253.861,288.925 h1.52
  text "4.17" at 270.367,288.925 h1.52
  text "2" at 180.476,285.877 h1.52
  text "L2" at 190.887,285.877 h1.52
  text "Copper Foil, 1/2oz (17um)" at 214.503,285.877 h1.52
  text "0.71mil" at 253.861,285.877 h1.52
  text "Dielectric 3" at 190.887,282.829 h1.52
  text "Isola 370HR Prepreg" at 214.503,282.829 h1.52
  text "5.91mil" at 253.861,282.829 h1.52
  text "4.17" at 270.367,282.829 h1.52
  text "3" at 180.476,279.781 h1.52
  text "L3" at 190.887,279.781 h1.52
  text "Copper Foil, 1/2oz (17um)" at 214.503,279.781 h1.52
  text "0.71mil" at 253.861,279.781 h1.52
  text "Dielectric1" at 190.887,276.733 h1.52
  text "Isola 370HR Core" at 214.503,276.733 h1.52
  text "39.37mil" at 253.861,276.733 h1.52
  text "4.17" at 270.367,276.733 h1.52
  text "4" at 180.476,273.685 h1.52
  text "L4" at 190.887,273.685 h1.52
  text "Copper Foil, 1/2oz (17um)" at 214.503,273.685 h1.52
  text "0.71mil" at 253.861,273.685 h1.52
  text "Dielectric 4" at 190.887,270.637 h1.52
  text "Isola 370HR Prepreg" at 214.503,270.637 h1.52
  text "5.91mil" at 253.861,270.637 h1.52
  text "4.17" at 270.367,270.637 h1.52
  text "5" at 180.476,267.589 h1.52
  text "L5" at 190.887,267.589 h1.52
  text "Copper Foil, 1/2oz (17um)" at 214.503,267.589 h1.52
  text "0.71mil" at 253.861,267.589 h1.52
  text "Dielectric 2" at 190.887,264.541 h1.52
  text "Isola 370HR Core" at 214.503,264.541 h1.52
  text "3.94mil" at 253.861,264.541 h1.52
  text "4.17" at 270.367,264.541 h1.52
  text "6" at 180.476,261.493 h1.52
  text "L6" at 190.887,261.493 h1.52
  text "Copper Foil, 1/2oz (17um)" at 214.503,261.493 h1.52
  text "0.71mil" at 253.861,261.493 h1.52
  text "Bottom Solder" at 190.887,258.445 h1.52
  text "Solder Resist" at 214.503,258.445 h1.52
  text "0.40mil" at 253.861,258.445 h1.52
  text "3.5" at 270.367,258.445 h1.52
  text "Bottom Overlay" at 190.887,255.397 h1.52
  text "Total board thickness:" at 180.476,252.349 h1.52
  text "64.11mil" at 253.861,252.349 h1.52
  text ".Layer_Name" at 14.656,-21.806 h1.52
M13 Component Bodies Top:
  text ".Layer_Name" at 14.656,-21.806 h1.52
M14 Component Bodies Bottom:
  text ".Layer_Name" at 14.656,-21.806 h1.52
M15 Courtyards Top:
  text ".Layer_Name" at 14.656,-21.806 h1.52
M16 Courtyards Bottom:
  text ".Layer_Name" at 14.656,-21.806 h1.52
Drill Drawing:
  circle w0.254: c101.819,289.964 r0.701
  lines w0.254: 101.118,273.493 101.819,273.843 102.52,273.493 102.17,274.194 102.52,274.895 101.819,274.544 101.118,274.895 101.469,274.194 101.118,273.493 ; 101.118,278.049 102.52,278.049 101.819,276.647 101.118,278.049 ; 101.118,279.801 102.52,279.801 102.52,281.203 101.118,281.203 101.118,279.801 ; 101.118,282.955 101.118,283.305 101.469,283.656 101.118,284.006 101.118,284.357 101.469,284.357 101.819,284.006 102.17,284.357 102.52,284.357 102.52,284.006 102.17,283.656 102.52,283.305 102.52,282.955 102.17,282.955 101.819,283.305 101.469,282.955 101.118,282.955 ; 101.118,286.459 101.469,286.459 101.469,286.109 102.17,286.109 102.17,286.459 102.52,286.459 102.52,287.16 102.17,287.16 102.17,287.511 101.469,287.511 101.469,287.16 101.118,287.16 101.118,286.459 ; 101.118,293.118 101.819,292.417 102.52,293.118 101.819,293.819 101.118,293.118 ; 101.118,295.571 102.52,295.571 102.52,296.973 101.118,296.973 101.118,295.571 ; 101.118,300.127 102.52,300.127 101.819,298.725 101.118,300.127 ; 101.399,295.852 102.24,295.852 102.24,296.693 101.399,296.693 101.399,295.852 ; 101.399,299.847 102.24,299.847 101.819,299.006 101.399,299.847
  lines w0.305: 99.847,272.546 174.946,272.546 ; 99.847,300.933 174.946,300.933 ; 108.429,269.392 108.429,304.087 ; 116.077,269.392 116.077,304.087 ; 131.097,269.392 131.097,304.087 ; 137.678,269.392 137.678,304.087 ; 147.207,269.392 147.207,304.087 ; 160.558,269.392 160.558,304.087 ; 99.847,269.392 174.946,269.392 174.946,304.087 99.847,304.087 99.847,269.392
  text "Symbol" at 101.74,301.879 h1.83
  text "Count" at 109.375,301.879 h1.83
  text "Hole Size" at 117.023,301.879 h1.83
  text "Plated" at 132.043,301.879 h1.83
  text "Hole Type" at 138.625,301.879 h1.83
  text "Drill Layer Pair" at 148.154,301.879 h1.83
  text "Hole Tolerance" at 161.504,301.879 h1.83
  text "24" at 109.375,298.725 h1.52
  text "0.200mm (7.87mil)" at 117.023,298.725 h1.52
  text "PTH" at 132.043,298.725 h1.52
  text "Round" at 138.625,298.725 h1.52
  text "L1 - L6" at 148.154,298.725 h1.52
  text "566" at 109.375,295.571 h1.52
  text "0.305mm (12.00mil)" at 117.023,295.571 h1.52
  text "PTH" at 132.043,295.571 h1.52
  text "Round" at 138.625,295.571 h1.52
  text "L1 - L6" at 148.154,295.571 h1.52
  text "188" at 109.375,292.417 h1.52
  text "0.457mm (18.00mil)" at 117.023,292.417 h1.52
  text "PTH" at 132.043,292.417 h1.52
  text "Round" at 138.625,292.417 h1.52
  text "L1 - L6" at 148.154,292.417 h1.52
  text "56" at 109.375,289.263 h1.52
  text "1.016mm (40.00mil)" at 117.023,289.263 h1.52
  text "PTH" at 132.043,289.263 h1.52
  text "Round" at 138.625,289.263 h1.52
  text "L1 - L6" at 148.154,289.263 h1.52
  text "2" at 109.375,286.109 h1.52
  text "1.020mm (40.16mil)" at 117.023,286.109 h1.52
  text "NPTH" at 132.043,286.109 h1.52
  text "Round" at 138.625,286.109 h1.52
  text "L1 - L6" at 148.154,286.109 h1.52
  text "6" at 109.375,282.955 h1.52
  text "1.020mm (40.16mil)" at 117.023,282.955 h1.52
  text "PTH" at 132.043,282.955 h1.52
  text "Round" at 138.625,282.955 h1.52
  text "L1 - L6" at 148.154,282.955 h1.52
  text "4" at 109.375,279.801 h1.52
  text "3.150mm (124.02mil)" at 117.023,279.801 h1.52
  text "PTH" at 132.043,279.801 h1.52
  text "Round" at 138.625,279.801 h1.52
  text "L1 - L6" at 148.154,279.801 h1.52
  text "6" at 109.375,276.647 h1.52
  text "3.200mm (125.98mil)" at 117.023,276.647 h1.52
  text "PTH" at 132.043,276.647 h1.52
  text "Round" at 138.625,276.647 h1.52
  text "L1 - L6" at 148.154,276.647 h1.52
  text "18" at 109.375,273.493 h1.52
  text "3.658mm (144.00mil)" at 117.023,273.493 h1.52
  text "PTH" at 132.043,273.493 h1.52
  text "Round" at 138.625,273.493 h1.52
  text "L1 - L6" at 148.154,273.493 h1.52
  text "870 Total" at 109.375,270.339 h1.52
  text ".Layer_Name" at 14.656,-21.806 h1.52
M17 Embedded Cavity:
  text ".Layer_Name" at 14.656,-21.806 h1.52
M18 Embedded Assembly:
  text ".Layer_Name" at 14.656,-21.806 h1.52
M19 Embedded Keepout:
  text ".Layer_Name" at 14.91,-21.552 h1.52

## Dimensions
107.62,177.8 to 97,183 on M2 Board Dimensions
246,196 to 238,204 on M2 Board Dimensions
246,196 to 250,200 on M2 Board Dimensions
250,200 to 246,196 on M2 Board Dimensions
97,177.8 to 107.62,150.8 on M2 Board Dimensions
99,177.8 to 99,123.8 on M2 Board Dimensions
147.155,105.455 to 128.105,106.725 on M2 Board Dimensions
222.885,104.775 to 203.835,106.045 on M2 Board Dimensions
100,200 to 120.32,235 on M2 Board Dimensions
100,200 to 107.62,205 on M2 Board Dimensions
251,200 to 251,100 on M2 Board Dimensions
0,-10.16 to 25.4,-10.16 on M2 Board Dimensions
250,99 to 100,99 on M2 Board Dimensions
